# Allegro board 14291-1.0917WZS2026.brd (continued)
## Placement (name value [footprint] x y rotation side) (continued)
PR8221  0R2J-2-GP  [R402H16]  201.47 95.13 90 bottom
PR8222  20KR2F-L-GP  [R402H16]  211.14 94.18 180 bottom
PR8223  2D2R3J-2-GP  [R603H22]  207.77 102.9 180 bottom
PR8224  5K76R2F-2-GP  [R402H16]  210.31 102.65 0 bottom
PR8256  1KR2J-1-GP  [R402H16]  214.14 96.68 90 bottom
PR8257  0R2J-2-GP  [R402H16]  215.76 95.66 90 bottom
PR8258  10KR2J-3-GP  [R402H16]  214.5 95.41 0 bottom
PR8259  10KR2J-3-GP  [R402H16]  212.72 95.41 180 bottom
PR8260  13KR2F-GP  [R402H16]  214.14 97.49 90 bottom
PR8301  2D2R2F-GP  [R402H16]  141.98 154.59 270 bottom
PR8302  10KR2F-2-GP  [R402H16]  144.52 150.51 180 bottom
PR8303  7K5R2F-1-GP  [R402H16]  143.66 150.51 0 bottom
PR8304  100KR2F-L1-GP  [R402H16]  149.03 151 0 bottom
PR8305  0R2J-2-GP  [R402H16]  145.86 151.52 270 bottom
PR8306  100R2J-2-GP  [R402H14]  181.53 146.16 0 top
PR8307  100KR2J-1-GP  [R402H16]  182.31 143.76 270 top
PR8308  1KR2J-1-GP  [R402H16]  146.3 150.24 0 bottom
PR8309  100R2J-2-GP  [R402H14]  217.16 99.98 90 bottom
PR8310  100KR2J-1-GP  [R402H16]  152.09 37 270 top
PR8311  100KR2J-1-GP  [R402H16]  157.58 40.56 0 top
PR8312  330KR2J-L1-GP  [R402H16]  152.09 36.11 270 top
PR8313  100R2J-2-GP  [R402H14]  159.03 34.88 180 top
PR8314  100KR2J-1-GP  [R402H16]  156.69 40.56 0 top
PR8315  100KR2J-1-GP  [R402H16]  217.45 95.92 90 bottom
PR8316  100R2J-2-GP  [R402H14]  166.51 143.33 270 bottom
PR8317  100KR2J-1-GP  [R402H16]  172.5 142.28 270 bottom
PR8318  100R2J-2-GP  [R402H14]  166.51 140.29 270 bottom
PR8319  100KR2J-1-GP  [R402H16]  172.15 140.05 270 bottom
PR8320  0R2J-2-GP  [R402H16]  149.91 151 180 bottom
PT4501  SE220U6D3VM-38-GP  [SE361414H178]  43.68 31.77 270 bottom
PT4502  SE220U6D3VM-38-GP  [SE361414H178]  28.98 31.92 90 bottom
PT4701  SE330U2VDM-L-GP  [CT7343H83]  126.61 114.33 270 bottom
PT4702  SE33U25VM-10-GP  [SE361413H182]  146.04 145.52 270 bottom
PT4703  SE33U25VM-10-GP  [SE361413H182]  128.95 137.88 270 bottom
PT4801  SE330U2VDM-L-GP  [CT7343H83]  101.39 113.31 90 bottom
PT8206  SE330U2VDM-L-GP  [CT7343H83]  216.02 130.84 270 bottom
PT8207  SE330U2VDM-L-GP  [CT7343H83]  202.69 123.6 90 bottom
PT8208  SE330U2D5VM-14-GP  [SE361414H178]  215.89 124.49 270 bottom
PU4301  SI7121DN-T1-GE3-GP  [PPAK-8P-2H45]  98.61 156.31 270 top
PU4401  BQ24780SRUYR-GP  [QFN28-G2D7H32]  106.57 160.23 0 bottom
PU4402  SI7121DN-T1-GE3-GP  [PPAK-8P-2H45]  98.96 151.84 90 top
PU4403  SI7121DN-T1-GE3-GP  [PPAK-8P-2H45]  137.28 158.53 180 bottom
PU4404  SIS412DN-T1-GE3-GP  [PPAK-8P-2H45]  121.91 157.38 270 bottom
PU4405  SIS412DN-T1-GE3-GP  [PPAK-8P-2H45]  123.39 162.03 90 bottom
PU4501  SIS412DN-T1-GE3-GP  [PPAK-8P-2H45]  47.52 44.98 0 top
PU4502  SIS780DN-T1-GE3-GP  [PPAK-8P-2H45]  42.95 43.46 180 top
PU4503  RT6576DGQW-GP  [QFN20-G1D75H32]  39.14 55.14 0 top
PU4504  SIS412DN-T1-GE3-GP  [PPAK-8P-2H45]  30.12 44.98 0 top
PU4505  SIS412DN-T1-GE3-GP  [PPAK-8P-2H45]  34.69 43.46 180 top
PU4601  NCP81208MNTXG-2-GP  [LFQFN48J6-G4D6H40]  113.91 143.79 90 top
PU4701  NCP81382MNTXG-1-GP  [QFN36J4060-G2554H40]  124.2 129.06 90 bottom
PU4801  NCP81382MNTXG-1-GP  [QFN36J4060-G2554H40]  110.87 128.55 90 bottom
PU5001  NCP81253MNTBG-1-GP  [LFDFN8G2-G1309H40]  134.86 137.82 0 top
PU5002  SIS412DN-T1-GE3-GP  [PPAK-8P-2H45]  137.15 129.95 180 bottom
PU5003  SIS412DN-T1-GE3-GP  [PPAK-8P-2H45]  132.58 128.43 0 bottom
PU5101  TPS51716RUKR-GP  [QFN20-G1D75H32]  47.87 22.25 90 top
PU5102  SIS412DN-T1-GE3-GP  [PPAK-8P-2H45]  58.92 24.79 90 top
PU5103  SIS780DN-T1-GE3-GP  [PPAK-8P-2H45]  60.45 20.22 270 top
PU5203  TPS22961DNYT-GP  [DFN8F3-G2517H32]  150.07 121.86 270 bottom
PU5301  SY8208DQNC-GP-U  [QFN10M3-G4P-UH34]  146.71 135.56 0 bottom
PU5401  APL5930KAI-TRG-GP  [SOIC8-G3530H63]  172.21 107.47 180 bottom
PU5402  S-1339D15-M5001-GP  [SOT-23-5H52]  39.22 17.65 90 top
PU8201  RT8812AGQW-GP  [QFN20-G1D75H32]  209.04 98.33 90 bottom
PU8202  FDMS3600-02-RJK0215-COLAY-GP  [PPAK-8P-G5324H44-COLAY]  215.66 108.42 90 top
PU8204  FDMS3600-02-RJK0215-COLAY-GP  [PPAK-8P-G5324H44-COLAY]  215.66 108.43 270 bottom
PU8206  FDMS3600-02-RJK0215-COLAY-GP  [PPAK-8P-G5324H44-COLAY]  202.94 108.74 270 top
PU8208  FDMS3600-02-RJK0215-COLAY-GP  [PPAK-8P-G5324H44-COLAY]  202.94 108.74 90 bottom
PU8301  RT8068AZQWID-GP-U  [DFN10G3-G265175H32]  146.04 154.21 90 bottom
PWR1  ACES-CON4-39-GP  [50503-0040N-W01]  216.7 165.67 0 top
PWSW2  SW-TACT-130-GP-U  [TJE-533-S-V-T-R-744]  216.6 174.07 0 top
Q1701  2N7002KDW-GP  [SOT-363H44]  153.86 72.29 90 bottom
Q1702  2N7002KDW-GP  [SOT-363H44]  161.13 68.57 270 bottom
Q1801  2N7002KDW-GP  [SOT-363H44]  148.47 100.93 270 top
Q1901  2N7002K-2-GP  [SOT23DGS2D4H44]  140.8 61.26 0 top
Q2408  2N7002K-2-GP  [SOT23DGS2D4H44]  163.02 76.24 180 top
Q2412  2N7002K-2-GP  [SOT23DGS2D4H44]  193.65 65.68 270 top
Q2413  2N7002K-2-GP  [SOT23DGS2D4H44]  161.79 70.11 0 top
Q2414  2N7002K-2-GP  [SOT23DGS2D4H44]  165.35 69.91 0 top
Q2416  2N7002K-2-GP  [SOT23DGS2D4H44]  182.73 56.08 90 top
Q2505  2N7002K-2-GP  [SOT23DGS2D4H44]  69.49 5.01 270 bottom
Q2601  2N7002KDW-GP  [SOT-363H44]  159.05 76.49 90 top
Q2602  2N7002K-2-GP  [SOT23DGS2D4H44]  162.18 96.23 90 bottom
Q2603  LMBT3904LT1G-GP  [SOT23CBE2D4H44]  53.97 61.24 270 bottom
Q2604  2N7002KDW-GP  [SOT-363H44]  162 75.96 180 bottom
Q3101  2N7002K-2-GP  [SOT23DGS2D4H44]  59.35 169.83 0 top
Q3102  LMBT3904LT1G-GP  [SOT23CBE2D4H44]  47.14 163.88 270 top
Q3103  LMBT3904LT1G-GP  [SOT23CBE2D4H44]  55.32 165.43 90 top
Q3104  DMP2130L-7-GP  [SOT23DGS2D4H48]  55.65 172.01 90 top
Q4001  2N7002KDW-GP  [SOT-363H44]  52.19 31.4 90 bottom
Q4002  MMBT2222A-3-GP  [SOT23CBE2D4H44]  29.82 54.01 90 top
Q4003  DMP2130L-7-GP  [SOT23DGS2D4H48]  166.75 100 0 bottom
Q4004  2N7002K-2-GP  [SOT23DGS2D4H44]  170.52 118.91 0 bottom
Q4008  DMP2130L-7-GP  [SOT23DGS2D4H48]  44.09 9.02 270 bottom
Q4009  2N7002K-2-GP  [SOT23DGS2D4H44]  49.8 13.07 270 bottom
Q5401  LMBT3904LT1G-GP  [SOT23CBE2D4H44]  20.57 75.98 0 bottom
Q5402  2N7002KDW-GP  [SOT-363H44]  16.38 69.5 270 top
Q5403  2N7002K-2-GP  [SOT23DGS2D4H44]  22.45 69.63 180 top
Q6001  2N7002KDW-GP  [SOT-363H44]  173.38 29.33 90 top
Q6101  2N7002KDW-GP  [SOT-363H44]  155.6 52.96 90 top
Q6401  DDTA143ECA-7-F-GP  [SOT23CBE2D4H44]  180.98 121.08 90 bottom
Q6402  2N7002K-2-GP  [SOT23DGS2D4H44]  178.08 117.47 90 bottom
Q6403  DDTA143ECA-7-F-GP  [SOT23CBE2D4H44]  181.86 110.14 90 bottom
Q6404  DDTA143ECA-7-F-GP  [SOT23CBE2D4H44]  181.86 106.58 90 bottom
Q6405  DDTA143ECA-7-F-GP  [SOT23CBE2D4H44]  181.89 116.8 90 bottom
Q6406  2N7002KDW-GP  [SOT-363H44]  181.48 102.99 0 bottom
Q6407  2N7002K-2-GP  [SOT23DGS2D4H44]  177.16 121.08 90 bottom
Q6408  2N7002KDW-GP  [SOT-363H44]  181 113.46 90 bottom
Q6501  DMN3404L-7-GP  [SOT23DGS2D4H48]  196.88 115.02 180 top
Q6502  DDTA143ECA-7-F-GP  [SOT23CBE2D4H44]  195.34 118.98 270 bottom
Q6503  2N7002KDW-GP  [SOT-363H44]  53.72 73.44 90 top
Q6504  DMP2130L-7-GP  [SOT23DGS2D4H48]  46.73 77.37 270 top
Q6505  2N7002K-2-GP  [SOT23DGS2D4H44]  42.03 75.85 180 top
Q6701  2N7002KDW-GP  [SOT-363H44]  175.67 90.62 270 bottom
Q7301  2N7002K-2-GP  [SOT23DGS2D4H44]  177.31 129.16 270 bottom
Q7601  2N7002KDW-GP  [SOT-363H44]  217.63 148.99 180 bottom
Q7602  2N7002KDW-GP  [SOT-363H44]  192.34 126.87 270 bottom
Q7606  2N7002K-2-GP  [SOT23DGS2D4H44]  209.7 134.21 270 top
Q9101  DMP2130L-7-GP  [SOT23DGS2D4H48]  157.05 26.48 90 bottom
Q9102  2N7002K-2-GP  [SOT23DGS2D4H44]  156.9 30.09 90 bottom
R307  0R0402-PAD-2-GP  [0R0402-PAD-1]  15.11 12.98 90 top
R401  1KR2J-1-GP  [R402H16]  91.45 98.9 90 bottom
R402  51R2J-2-GP  [R402H16]  103.42 98.63 0 bottom
R403  499R2F-2-GP  [R402H16]  90.29 97.99 270 bottom
R404  0R0402-PAD-1-GP  [0R0402-PAD]  91.33 100.28 180 bottom
R405  10KR2J-3-GP  [R402H16]  91.21 95.53 90 bottom
R406  51R2J-2-GP  [R402H16]  100.91 103.31 0 bottom
R407  51R2J-2-GP  [R402H16]  107.11 102.4 0 bottom
R408  51R2J-2-GP  [R402H16]  105.82 101.88 0 bottom
R409  51R2J-2-GP  [R402H16]  107.12 104.69 0 bottom
R412  49D9R2F-GP  [R402H16]  125.79 64.33 0 top
R413  49D9R2F-GP  [R402H16]  126.98 64.34 0 top
R416  51R2J-2-GP  [R402H16]  105.41 103.14 270 bottom
R417  1KR2J-1-GP  [R402H16]  105.4 103.96 270 bottom
R419  1KR2J-1-GP  [R402H16]  99.77 103.11 0 bottom
R420  0R2J-2-GP  [R402H16]  98.18 106.32 90 bottom
R421  51R2J-2-GP  [R402H16]  102.79 103.56 0 bottom
R422  51R2J-2-GP  [R402H16]  103.67 104.09 0 bottom
R423  51R2J-2-GP  [R402H16]  101.98 103.56 0 bottom
R501  121R2F-GP  [R402H16]  123.4 73.15 0 top
R502  80D6R2F-L-GP  [R402H16]  124.29 73.15 0 top
R503  100R2F-L1-GP-U  [R402H14]  125.18 73.15 0 top
R504  0R0402-PAD-1-GP  [0R0402-PAD]  150.03 66.95 0 top
R505  470R2F-GP  [R402H16]  149.12 66.95 180 top
R601  49D9R2F-GP  [R402H16]  87.11 90.52 90 bottom
R602  0R0402-PAD-1-GP  [0R0402-PAD]  87.86 66.89 180 bottom
R603  100KR2J-1-GP  [R402H16]  97.38 99.47 0 bottom
R604  1KR2J-1-GP  [R402H16]  87.24 96.04 90 bottom
R605  1KR2J-1-GP  [R402H16]  90.24 93.55 90 bottom
R705  0R0603-PAD-1-GP-U  [0R0603-PAD-U]  130.04 62.13 90 top
R709  0R0402-PAD-2-GP  [0R0402-PAD-1]  98.39 100.59 0 bottom
R719  100R2F-L1-GP-U  [R402H14]  117.32 93.86 0 top
R720  100R2F-L1-GP-U  [R402H14]  116.5 93.86 180 top
R721  100R2F-L1-GP-U  [R402H14]  87.77 87.52 180 bottom
R722  100R2F-L1-GP-U  [R402H14]  87.77 85.84 180 bottom
R723  54D9R2F-L1-GP  [R402H16]  98.67 102.72 0 bottom
R726  100R2F-L1-GP-U  [R402H14]  98.39 98.86 180 bottom
R727  56R2J-4-GP  [R402H16]  99.63 100.34 180 bottom
R728  220R2J-L2-GP  [R402H16]  99.63 98.61 180 bottom
R730  100R2F-L1-GP-U  [R402H14]  120.95 81.56 180 top
R732  0R0402-PAD-2-GP  [0R0402-PAD-1]  100.48 100.33 0 bottom
R733  100R2F-L1-GP-U  [R402H14]  119.81 79.09 90 top
R734  100R2F-L1-GP-U  [R402H14]  120.12 98.63 0 bottom
R735  100R2F-L1-GP-U  [R402H14]  122.87 98.25 90 bottom
R801  24D9R2F-L-GP  [R402H16]  108.77 90.81 270 top
R802  10KR2J-3-GP  [R402H16]  141.92 93.16 180 top
R803  2K2R2J-2-GP  [R402H16]  142.82 91.22 0 top
R804  2K2R2J-2-GP  [R402H16]  142.9 93.48 0 top
R805  0R0402-PAD-2-GP  [0R0402-PAD-1]  153.91 93.94 90 top
R806  100KR2J-1-GP  [R402H16]  153.73 91.56 270 bottom
R807  0R2J-2-GP  [R402H16]  153.91 93.13 90 top
R1101  0R3J-0-U-GP  [R603H22]  147.16 103.48 90 bottom
R1102  0R3J-0-U-GP  [R603H22]  147.37 98.53 90 bottom
R1103  0R0805-PAD-1-GP-U  [0R0805-PAD-U]  152.61 117.69 270 bottom
R1104  0R3J-0-U-GP  [R603H22]  139.29 111.14 90 top
R1105  0R5J-5-GP  [R805H24]  152.61 115.86 270 bottom
R1106  0R0805-PAD-1-GP-U  [0R0805-PAD-U]  166.23 88.19 180 bottom
R1107  0R5J-5-GP  [R805H24]  155.09 120.13 0 bottom
R1108  0R0603-PAD-1-GP-U  [0R0603-PAD-U]  160.44 88.65 0 bottom
R1109  0R0603-PAD-1-GP-U  [0R0603-PAD-U]  165.22 81.48 270 bottom
R1110  0R0603-PAD-1-GP-U  [0R0603-PAD-U]  160.97 78.89 270 bottom
R1111  0R3J-0-U-GP  [R603H22]  167.11 81.9 180 bottom
R1112  0R0603-PAD-1-GP-U  [0R0603-PAD-U]  161.57 91.98 180 bottom
R1113  0R0603-PAD-1-GP-U  [0R0603-PAD-U]  159.13 88.66 180 bottom
R1114  0R0603-PAD-1-GP-U  [0R0603-PAD-U]  143.94 105.34 180 bottom
R1115  0R0603-PAD-1-GP-U  [0R0603-PAD-U]  162.72 84.22 270 bottom
R1116  0R0603-PAD-1-GP-U  [0R0603-PAD-U]  165.27 79.51 180 bottom
R1117  0R0603-PAD-1-GP-U  [0R0603-PAD-U]  148.51 115.4 270 bottom
R1118  0R3J-0-U-GP  [R603H22]  156.65 87.06 270 bottom
R1119  0R3J-0-U-GP  [R603H22]  142.67 98.73 90 bottom
R1120  0R3J-0-U-GP  [R603H22]  160.32 93.81 90 bottom
R1121  0R0603-PAD-1-GP-U  [0R0603-PAD-U]  147.01 104.84 270 bottom
R1122  0R0603-PAD-1-GP-U  [0R0603-PAD-U]  135.04 104.33 270 top
R1123  0R0603-PAD-1-GP-U  [0R0603-PAD-U]  159.79 85.52 90 bottom
R1124  0R0603-PAD-1-GP-U  [0R0603-PAD-U]  162.8 89.57 270 bottom
R1125  0R0603-PAD-1-GP-U  [0R0603-PAD-U]  140.21 104.29 270 bottom
R1126  0R0603-PAD-1-GP-U  [0R0603-PAD-U]  163.49 79.26 180 bottom
R1127  0R0603-PAD-1-GP-U  [0R0603-PAD-U]  162.8 88.15 270 bottom
R1128  0R0603-PAD-1-GP-U  [0R0603-PAD-U]  159.8 84.23 90 bottom
R1129  0R3J-0-U-GP  [R603H22]  156.65 88.34 270 bottom
R1130  0R0603-PAD-1-GP-U  [0R0603-PAD-U]  164.66 91.43 90 bottom
R1131  0R0603-PAD-1-GP-U  [0R0603-PAD-U]  134.96 104.39 90 bottom
R1132  0R0603-PAD-1-GP-U  [0R0603-PAD-U]  138.27 104.78 180 bottom
R1133  0R0603-PAD-1-GP-U  [0R0603-PAD-U]  162.84 91.98 180 bottom
R1134  0R0603-PAD-1-GP-U  [0R0603-PAD-U]  163.42 93.81 270 bottom
R1135  0R0603-PAD-1-GP-U  [0R0603-PAD-U]  159.78 86.8 90 bottom
R1136  0R3J-0-U-GP  [R603H22]  156.67 85.78 270 bottom
R1138  0R0603-PAD-1-GP-U  [0R0603-PAD-U]  154.28 88.36 270 bottom
R1139  0R0603-PAD-1-GP-U  [0R0603-PAD-U]  156.64 89.64 270 bottom
R1201  0R0402-PAD-2-GP  [0R0402-PAD-1]  124.71 38.08 180 top
R1202  0R0402-PAD-2-GP  [0R0402-PAD-1]  123.83 38.08 180 top
R1301  0R0402-PAD-2-GP  [0R0402-PAD-1]  137.52 25.81 0 top
R1302  10KR2J-3-GP  [R402H16]  139.52 25.73 180 top
R1501  100R2F-L1-GP-U  [R402H14]  132.81 93.92 90 top
R1502  200R2F-L-GP  [R402H16]  139.26 76.76 270 bottom
R1503  10KR2J-3-GP  [R402H16]  137.17 101.76 0 bottom
R1603  113R2F-GP  [R402H16]  140.39 83.6 90 top
R1604  100R2F-L1-GP-U  [R402H14]  139.65 96.27 0 bottom
R1606  10KR2J-3-GP  [R402H16]  139.69 92.88 90 bottom
R1607  10KR2J-3-GP  [R402H16]  135.84 64.23 180 bottom
R1608  10KR2J-3-GP  [R402H16]  140.13 91.62 180 bottom
R1609  10KR2J-3-GP  [R402H16]  141.93 91.21 0 top
R1701  3KR2J-2-GP  [R402H16]  136.14 102.07 180 bottom
R1702  1KR2J-1-GP  [R402H16]  151.12 73.72 90 bottom
R1703  1KR2J-1-GP  [R402H16]  153.82 66.99 270 top
R1704  0R0402-PAD-2-GP  [0R0402-PAD-1]  141.02 57.34 270 top
R1705  0R0402-PAD-1-GP  [0R0402-PAD]  153.82 66.16 270 top
R1706  0R0402-PAD-1-GP  [0R0402-PAD]  139.33 57.18 270 top
R1707  10KR2J-3-GP  [R402H16]  151.72 66.96 180 top
R1708  0R0603-PAD-1-GP-U  [0R0603-PAD-U]  166.03 70.38 180 bottom
R1709  10KR2J-3-GP  [R402H16]  159.66 65.77 270 bottom
R1710  0R2J-2-GP  [R402H16]  85.92 94.2 0 bottom
R1711  0R0603-PAD-1-GP-U  [0R0603-PAD-U]  162.78 86.83 270 bottom
R1712  0R3J-0-U-GP  [R603H22]  162.74 85.5 270 bottom
R1713  0R0402-PAD-1-GP  [0R0402-PAD]  155.09 75.06 90 bottom
R1714  10KR2J-3-GP  [R402H16]  157.57 70.53 270 top
R1715  100KR2J-1-GP  [R402H16]  154.84 74.23 90 bottom
R1716  100KR2F-L1-GP  [R402H16]  94.58 100.86 270 bottom
R1717  10KR2J-3-GP  [R402H16]  140.5 96.26 180 bottom
R1718  0R2J-2-GP  [R402H16]  135.25 48.91 270 bottom
R1719  47KR2F-GP  [R402H16]  96.11 98.23 270 bottom
R1720  0R0603-PAD-1-GP-U  [0R0603-PAD-U]  164.12 68.84 90 bottom
R1721  0R2J-2-GP  [R402H16]  161 54.97 180 top
R1722  1KR2J-1-GP  [R402H16]  95.43 100.03 270 bottom
R1723  10KR2J-3-GP  [R402H16]  153.81 67.84 270 top
R1724  0R0805-PAD-1-GP-U  [0R0805-PAD-U]  157.13 109.21 180 bottom
R1725  100KR2F-L1-GP  [R402H16]  136.95 48.91 90 bottom
R1726  10KR2J-3-GP  [R402H16]  152.86 70.35 90 bottom
R1727  100KR2J-1-GP  [R402H16]  151.57 71.64 0 bottom
R1728  0R0402-PAD-2-GP  [0R0402-PAD-1]  150.74 71.63 180 bottom
R1729  0R2J-2-GP  [R402H16]  151.13 72.9 90 bottom
R1730  330KR2J-L1-GP  [R402H16]  152.55 66.94 180 top
R1731  20KR2J-L2-GP  [R402H16]  144.17 78.74 0 top
R1732  10KR2F-2-GP  [R402H16]  138.73 58.44 0 top
R1733  10KR2J-3-GP  [R402H16]  139.63 58.45 0 top
R1734  60D4R2F-GP  [R402H16]  94.4 98.23 90 bottom
R1735  0R0805-PAD-1-GP-U  [0R0805-PAD-U]  155.22 109.21 180 bottom
R1736  0R2J-2-GP  [R402H16]  150.87 66.95 180 top
R1737  100KR2J-1-GP  [R402H16]  158.89 68.61 0 bottom
R1801  0R0402-PAD-1-GP  [0R0402-PAD]  132.69 62.23 0 bottom
R1802  1MR2J-1-GP  [R402H16]  119.9 101.09 270 bottom
R1803  2K7R2F-GP  [R402H16]  122.07 88.03 0 top
R1804  22R2J-2-GP  [R402H16]  132.2 64.42 0 top
R1805  22R2J-2-GP  [R402H16]  136.37 64.34 0 top
R1806  10R2F-L-GP  [R402H14]  144.63 66.55 0 bottom
R1807  10R2F-L-GP  [R402H14]  136.5 67.08 270 bottom
R1808  10R2F-L-GP  [R402H14]  143.8 66.54 0 bottom
R1809  10R2F-L-GP  [R402H14]  139.8 66.74 0 bottom
R1810  0R0402-PAD-1-GP  [0R0402-PAD]  119.91 101.91 270 bottom
R1811  10R2F-L-GP  [R402H14]  141.63 75.09 90 bottom
R1812  0R0402-PAD-1-GP  [0R0402-PAD]  145.47 65.46 0 bottom
R1813  0R0402-PAD-1-GP  [0R0402-PAD]  128.94 64.34 0 top
R1814  10KR2J-3-GP  [R402H16]  135.03 64.24 0 bottom
R1815  10MR2J-L-GP  [R402H16]  145.71 77.18 0 bottom
R1816  0R0402-PAD-1-GP  [0R0402-PAD]  139.34 74.2 90 bottom
R1817  10KR2J-3-GP  [R402H16]  140.5 64.36 180 top
R1818  8K2R2F-1-GP  [R402H16]  133.85 64.34 0 top
R1819  0R0402-PAD-1-GP  [0R0402-PAD]  134.69 64.34 0 top
R1820  150KR2F-L-GP  [R402H16]  148.09 83.11 90 bottom
R1821  2K2R2J-2-GP  [R402H16]  148.09 81.96 270 bottom
R1822  1KR2J-1-GP  [R402H16]  146.4 84.18 180 bottom
R1823  1KR2J-1-GP  [R402H16]  140.45 84.44 90 top
R1824  1KR2J-1-GP  [R402H16]  141.34 66.54 0 bottom
R1825  1KR2J-1-GP  [R402H16]  142.15 66.54 180 bottom
R1826  1KR2J-1-GP  [R402H16]  142.98 66.55 0 bottom
R1827  1KR2J-1-GP  [R402H16]  138.98 66.74 0 bottom
R1828  0R2J-2-GP  [R402H16]  139.33 73.36 90 bottom
R1829  10KR2J-3-GP  [R402H16]  144.53 64.25 180 top
R1830  10KR2J-3-GP  [R402H16]  143.71 64.25 180 top
R1831  10KR2J-3-GP  [R402H16]  137.19 64.34 180 top
R1832  10KR2J-3-GP  [R402H16]  139.68 64.36 180 top
R1833  10KR2J-3-GP  [R402H16]  142.76 64.24 180 top
R1834  1KR2J-1-GP  [R402H16]  138.86 67.99 90 bottom
R1835  1KR2J-1-GP  [R402H16]  140.14 75.49 180 bottom
R1836  1KR2J-1-GP  [R402H16]  139.15 75.5 0 bottom
R1901  200R2F-L-GP  [R402H16]  140.45 85.41 90 top
R1902  10KR2J-3-GP  [R402H16]  137.76 60.14 0 top
R1904  100KR2J-1-GP  [R402H16]  134.63 98.7 180 bottom
R1907  33R2J-2-GP  [R402H16]  135.25 45.67 90 bottom
R1908  0R0402-PAD-1-GP  [0R0402-PAD]  135.24 46.72 90 bottom
R1909  1KR2J-1-GP  [R402H16]  135.7 44 90 bottom
R1910  0R2J-2-GP  [R402H16]  142.74 100.37 270 top
R1911  0R0402-PAD-1-GP  [0R0402-PAD]  135.24 47.55 90 bottom
R1912  33R2J-2-GP  [R402H16]  135.25 44.84 90 bottom
R1913  0R2J-2-GP  [R402H16]  142.75 101.24 270 top
R2002  10KR2J-3-GP  [R402H16]  144.4 82.6 270 bottom
R2003  0R2J-2-GP  [R402H16]  143.32 75.06 90 bottom
R2004  0R2J-2-GP  [R402H16]  146.85 65.99 270 top
R2005  10KR2J-3-GP  [R402H16]  142.71 81.81 90 bottom
R2006  1KR2J-1-GP  [R402H16]  141.9 64.24 180 top
R2007  1KR2J-1-GP  [R402H16]  149.33 72.18 270 top
R2008  10KR2J-3-GP  [R402H16]  142.7 82.64 270 bottom
R2009  10KR2J-3-GP  [R402H16]  135.36 69.28 90 bottom
R2015  10KR2J-3-GP  [R402H16]  139.3 64.26 0 bottom
R2016  10KR2J-3-GP  [R402H16]  138.45 64.26 180 bottom
R2017  10KR2J-3-GP  [R402H16]  140.26 64.28 0 bottom
R2018  10KR2J-3-GP  [R402H16]  141.09 63.5 180 bottom
R2019  1KR2J-1-GP  [R402H16]  149.34 73.04 90 top
R2021  10KR2J-3-GP  [R402H16]  134.18 64.23 0 bottom
R2023  10KR2J-3-GP  [R402H16]  148.27 74.05 270 top
R2024  10KR2J-3-GP  [R402H16]  148.27 74.89 90 top
R2025  10KR2J-3-GP  [R402H16]  142.77 63.31 0 bottom
R2026  10KR2J-3-GP  [R402H16]  141.94 63.51 180 bottom
R2032  10KR2J-3-GP  [R402H16]  136.72 64.25 0 bottom
R2033  10KR2J-3-GP  [R402H16]  146.27 64.29 180 top
R2034  10KR2J-3-GP  [R402H16]  145.42 64.29 0 top
R2039  10KR2J-3-GP  [R402H16]  149.32 71.31 270 top
R2040  10KR2J-3-GP  [R402H16]  148.37 86.79 0 bottom
R2041  10KR2J-3-GP  [R402H16]  139.3 79.98 90 bottom
R2043  10KR2J-3-GP  [R402H16]  142.76 78.13 90 bottom
R2044  10KR2J-3-GP  [R402H16]  143.15 88.6 270 top
R2045  0R0402-PAD-1-GP  [0R0402-PAD]  136.62 68.84 180 bottom
R2046  51KR2J-1-GP  [R402H16]  144.4 81.76 90 bottom
R2047  10KR2J-3-GP  [R402H16]  143.15 87.78 270 top
R2048  51KR2J-1-GP  [R402H16]  139.3 80.8 270 bottom
R2049  51KR2J-1-GP  [R402H16]  139.84 81.63 270 bottom
R2050  10KR2J-3-GP  [R402H16]  142.69 77.28 90 bottom
R2051  10KR2J-3-GP  [R402H16]  89.28 150.93 270 bottom
R2106  0R0603-PAD-1-GP-U  [0R0603-PAD-U]  130.6 64.58 270 top
R2401  0R2J-2-GP  [R402H16]  172.45 62.66 0 top
R2402  0R0402-PAD-1-GP  [0R0402-PAD]  171.8 65.77 180 top
R2409  100KR2J-1-GP  [R402H16]  177.91 84.79 90 bottom
R2410  0R0402-PAD-1-GP  [0R0402-PAD]  172.94 87.41 180 top
R2411  0R0402-PAD-2-GP  [0R0402-PAD-1]  171.31 79.73 270 top
R2412  0R0402-PAD-2-GP  [0R0402-PAD-1]  191.47 70.22 90 top
R2414  4K7R2J-2-GP  [R402H16]  159.63 18.31 180 bottom
R2415  10KR2J-3-GP  [R402H16]  174.03 69.33 180 bottom
R2416  0R0402-PAD-1-GP  [0R0402-PAD]  161.95 73.29 0 top
R2417  100KR2J-1-GP  [R402H16]  164.56 72.21 270 top
R2418  0R2J-2-GP  [R402H16]  164.44 73.49 180 top
R2419  0R0402-PAD-1-GP  [0R0402-PAD]  191.82 78.16 90 top
R2420  10KR2J-3-GP  [R402H16]  183.68 61.75 0 top
R2421  330R2J-3-GP  [R402H16]  179.28 57.08 180 top
R2422  330R2J-3-GP  [R402H16]  182.4 67.51 180 bottom
R2423  330R2J-3-GP  [R402H16]  184.13 67.07 270 bottom
R2424  20KR2F-L-GP  [R402H16]  192.72 76.81 0 top
R2427  0R2J-2-GP  [R402H16]  191.57 83.71 90 top
R2428  0R2J-2-GP  [R402H16]  179.4 61.1 0 top
R2429  10KR2J-3-GP  [R402H16]  186.64 84.74 90 top
R2430  10KR2J-3-GP  [R402H16]  186.63 83.88 90 top
R2431  0R0402-PAD-1-GP  [0R0402-PAD]  188.6 84.33 0 top
R2432  1KR2J-1-GP  [R402H16]  190.17 63.95 90 top
R2433  100KR2J-1-GP  [R402H16]  185.16 84.55 180 top
R2434  100KR2J-1-GP  [R402H16]  191.47 71.06 270 top
R2435  0R0402-PAD-1-GP  [0R0402-PAD]  171.77 70.41 0 top
R2436  100KR2J-1-GP  [R402H16]  170.94 70.41 180 top
R2437  43R2J-GP  [R402H16]  170.62 68.83 270 top
R2438  10KR2J-3-GP  [R402H16]  191.13 67.44 0 top
R2440  0R2J-2-GP  [R402H16]  170.12 65.77 180 top
R2441  100KR2F-L1-GP  [R402H16]  184.57 53.76 90 top
R2442  64K9R2F-1-GP  [R402H16]  182.82 53.73 90 top
R2443  10KR2F-2-GP  [R402H16]  172.33 56.29 90 top
R2444  100KR2F-L1-GP  [R402H16]  173.6 54.89 0 top
R2445  0R0402-PAD-1-GP  [0R0402-PAD]  182.09 59.12 270 top
R2446  0R0603-PAD-1-GP-U  [0R0603-PAD-U]  182.63 61.93 0 top
R2448  10KR2F-2-GP  [R402H16]  191.05 76.89 0 top
R2449  100KR2J-1-GP  [R402H16]  171.3 78.91 90 top
R2450  100KR2J-1-GP  [R402H16]  171.31 78.09 270 top
R2451  100KR2J-1-GP  [R402H16]  188.91 64.35 0 top
R2452  100KR2J-1-GP  [R402H16]  188.45 59.77 90 top
R2454  100KR2J-1-GP  [R402H16]  186.35 66.67 0 bottom
R2457  0R2J-2-GP  [R402H16]  191.96 68.96 0 top
R2458  0R0402-PAD-1-GP  [0R0402-PAD]  178.57 62.13 0 top
R2462  0R0402-PAD-1-GP  [0R0402-PAD]  179.04 87.98 90 top
R2463  0R2J-2-GP  [R402H16]  155.79 18.3 0 bottom
R2464  0R2J-2-GP  [R402H16]  156.82 18.3 0 bottom
R2465  0R2J-2-GP  [R402H16]  158.74 18.31 0 bottom
R2466  0R2J-2-GP  [R402H16]  157.71 18.3 0 bottom
R2467  1KR2J-1-GP  [R402H16]  185.52 66.69 0 bottom
R2469  0R0402-PAD-1-GP  [0R0402-PAD]  190.57 62.47 180 top
R2470  0R0402-PAD-1-GP  [0R0402-PAD]  192.57 75.49 270 top
R2472  0R2J-2-GP  [R402H16]  181.47 52.92 180 top
R2473  0R0402-PAD-1-GP  [0R0402-PAD]  180.53 52.9 180 top
R2476  0R2J-2-GP  [R402H16]  154.53 17.87 90 bottom
R2478  100KR2J-1-GP  [R402H16]  171.6 76.02 270 top
R2479  0R0402-PAD-2-GP  [0R0402-PAD-1]  191.48 71.91 270 top
R2481  0R0402-PAD-1-GP  [0R0402-PAD]  182.33 88.09 0 top
R2482  0R0603-PAD-1-GP-U  [0R0603-PAD-U]  164.16 76.58 180 bottom
R2483  0R0603-PAD-1-GP-U  [0R0603-PAD-U]  159.82 76.66 0 bottom
R2484  100KR2J-1-GP  [R402H16]  191.14 65.76 180 top
R2485  10R2F-L-GP  [R402H14]  191.62 81.62 270 top
R2486  10R2F-L-GP  [R402H14]  191.62 79.91 270 top
R2487  10R2F-L-GP  [R402H14]  191.62 80.74 270 top
R2488  100KR2J-1-GP  [R402H16]  161.82 67.8 270 top
R2489  100KR2J-1-GP  [R402H16]  165.99 67.61 270 top
R2490  0R0402-PAD-1-GP  [0R0402-PAD]  191.62 79.06 270 top
R2491  0R0402-PAD-1-GP  [0R0402-PAD]  178.86 78.52 0 bottom
R2492  0R2J-2-GP  [R402H16]  170.96 65.77 180 top
R2493  0R2J-2-GP  [R402H16]  177.67 56.29 270 top
R2494  0R2J-2-GP  [R402H16]  175.89 56.29 90 top
R2495  0R2J-2-GP  [R402H16]  174.11 56.29 270 top
R2496  100KR2J-1-GP  [R402H16]  168.03 79.7 270 top
R2497  0R0402-PAD-2-GP  [0R0402-PAD-1]  177.16 52.23 270 top
R2498  100KR2J-1-GP  [R402H16]  184.36 58.62 90 top
R2499  0R0402-PAD-2-GP  [0R0402-PAD-1]  173.41 62.66 0 top
R2501  4K7R2J-2-GP  [R402H16]  147.49 56.01 270 bottom
R2502  1KR2J-1-GP  [R402H16]  69.3 7.64 0 bottom
R2503  10R2F-L-GP  [R402H14]  146.31 55.35 90 top
R2504  10MR2J-L-GP  [R402H16]  53.38 8.76 0 bottom
R2505  10R2F-L-GP  [R402H14]  140.28 54.91 0 top
R2506  10R2F-L-GP  [R402H14]  141.37 53.14 90 top
R2507  10R2F-L-GP  [R402H14]  147.49 55.17 90 bottom
R2508  10R2F-L-GP  [R402H14]  147.99 53.49 90 bottom
R2509  10R2F-L-GP  [R402H14]  152.07 52.1 0 bottom
R2510  10KR2F-2-GP  [R402H16]  175.21 84.89 180 top
R2511  10R2F-L-GP  [R402H14]  145.36 44.76 90 bottom
R2512  10R2F-L-GP  [R402H14]  145.36 43.03 90 bottom
R2513  10R2F-L-GP  [R402H14]  155.63 54.2 180 bottom
R2514  10R2F-L-GP  [R402H14]  151.39 54.6 270 bottom
R2515  4K7R2J-2-GP  [R402H16]  155.62 51.88 90 bottom
R2601  0R2J-2-GP  [R402H16]  159.35 94.87 270 bottom
R2602  0R0402-PAD-2-GP  [0R0402-PAD-1]  161.09 99.58 270 bottom
R2603  18K7R2F-GP  [R402H16]  149.27 95.43 270 bottom
R2604  2KR2F-3-GP  [R402H16]  159.53 97.59 180 bottom
R2605  0R2J-2-GP  [R402H16]  91.51 141.56 270 bottom
R2606  0R0402-PAD-2-GP  [0R0402-PAD-1]  98.36 145.54 90 top
R2607  10KR2J-3-GP  [R402H16]  161.09 100.39 270 bottom
R2608  25K5R2F-GP  [R402H16]  155.19 98.96 90 bottom
R2609  24K9R2F-L-GP  [R402H16]  155.19 99.85 90 bottom
R2610  NTC-100K-8-GP  [NTC-603H38]  153.66 99.85 0 bottom
R2611  0R0402-PAD-2-GP  [0R0402-PAD-1]  193.92 69.82 0 top
R2612  0R2J-2-GP  [R402H16]  162.38 99.95 0 bottom
R2702  0R0805-PAD-1-GP-U  [0R0805-PAD-U]  35.35 10.11 270 top
R2703  0R0603-PAD-1-GP-U  [0R0603-PAD-U]  20.93 25.66 180 top
R2704  0R0805-PAD-1-GP-U  [0R0805-PAD-U]  35.35 8.31 270 top
R2705  0R2J-2-GP  [R402H16]  25.15 8.1 180 top
R2706  0R0603-PAD-1-GP-U  [0R0603-PAD-U]  27.43 26.03 180 top
R2707  20KR2F-L-GP  [R402H16]  28.39 23.07 180 top
R2708  0R0402-PAD-2-GP  [0R0402-PAD-1]  32.23 9.75 270 top
R2709  200KR2F-L-GP  [R402H16]  29.26 22.17 180 top
R2710  0R2J-2-GP  [R402H16]  24.34 8.1 180 top
R2711  100KR2J-1-GP  [R402H16]  20.72 19.71 90 top
R2712  0R0402-PAD-2-GP  [0R0402-PAD-1]  22.06 25.5 180 top
R2713  0R0402-PAD-2-GP  [0R0402-PAD-1]  23.87 8.52 270 bottom
R2714  22R2J-2-GP  [R402H16]  33.07 13.42 270 top
R2715  0R2J-2-GP  [R402H16]  31.31 21.31 180 top
R2716  22R2J-2-GP  [R402H16]  33.87 14.69 270 top
R2717  1KR2J-1-GP  [R402H16]  32.56 23.8 0 top
R2718  22R2J-2-GP  [R402H16]  33.95 18.49 270 top
R2719  0R0402-PAD-2-GP  [0R0402-PAD-1]  35.61 19.77 0 top
R2720  22R2J-2-GP  [R402H16]  33.6 16.35 270 top
R2721  0R2J-2-GP  [R402H16]  32.47 22.07 0 top
R2722  100KR2J-1-GP  [R402H16]  29.86 24.01 270 top
R2723  0R0402-PAD-2-GP  [0R0402-PAD-1]  30.81 22.58 90 top
R2724  0R2J-2-GP  [R402H16]  32.66 11.31 0 top
R2725  0R2J-2-GP  [R402H16]  23.53 8.1 180 top
R2726  0R0402-PAD-2-GP  [0R0402-PAD-1]  22.71 8.1 180 top
R2727  0R0603-PAD-1-GP-U  [0R0603-PAD-U]  13.65 15.36 0 bottom
R2728  0R0402-PAD-2-GP  [0R0402-PAD-1]  52.1 13.83 180 bottom
R2729  0R2J-2-GP  [R402H16]  52.1 12.13 0 bottom
R2730  0R0603-PAD-1-GP-U  [0R0603-PAD-U]  29.28 25.33 90 top
R2731  0R0805-PAD-1-GP-U  [0R0805-PAD-U]  32.86 26.73 270 top
R2732  0R2J-2-GP  [R402H16]  34.21 15.52 90 top
R2906  0R0603-PAD-1-GP-U  [0R0603-PAD-U]  19.69 11.22 90 top
R2907  0R0603-PAD-1-GP-U  [0R0603-PAD-U]  13.89 11.33 270 top
R2908  10R2F-L-GP  [R402H14]  20.93 15.19 270 top
R2909  0R0603-PAD-1-GP-U  [0R0603-PAD-U]  12.11 14.98 180 top
R2910  10R2F-L-GP  [R402H14]  17.93 17.94 270 top
R2911  0R0603-PAD-1-GP-U  [0R0603-PAD-U]  16.97 9.13 180 top
R2912  4K7R2J-2-GP  [R402H16]  20.93 16 270 top
R2913  4K7R2J-2-GP  [R402H16]  17.93 18.78 270 top
R2919  10KR2J-3-GP  [R402H16]  18.99 16.01 270 top
R2920  10KR2J-3-GP  [R402H16]  18.08 23.36 180 top
R2921  1KR2J-1-GP  [R402H16]  18.94 23.37 0 top
R2922  1KR2J-1-GP  [R402H16]  18.21 21.97 270 top
R2923  0R0603-PAD-1-GP-U  [0R0603-PAD-U]  18.44 12.77 90 top
R3101  0R0603-PAD-1-GP-U  [0R0603-PAD-U]  50.23 172.55 180 top
R3102  10KR2J-3-GP  [R402H16]  43.83 163.01 0 top
R3103  10KR2J-3-GP  [R402H16]  50.82 163.06 0 top
R3104  0R0402-PAD-2-GP  [0R0402-PAD-1]  49.97 163.06 0 top
R3105  0R0603-PAD-1-GP-U  [0R0603-PAD-U]  53.07 171.33 0 top
R3106  1KR2J-1-GP  [R402H16]  51.84 167.98 270 top
R3107  15KR2J-1-GP  [R402H16]  51.86 167.06 90 top
R3108  0R0402-PAD-2-GP  [0R0402-PAD-1]  56.02 167.85 270 top
R3109  10KR2J-3-GP  [R402H16]  60.3 173.06 90 top
R3110  20KR2J-L2-GP  [R402H16]  60.3 172.18 270 top
R3111  100KR2J-1-GP  [R402H16]  60.3 167.54 90 top
R3112  2K49R2F-GP  [R402H16]  42.51 172.91 90 top
R3113  10KR2J-3-GP  [R402H16]  51.84 168.83 90 top
R3114  0R0402-PAD-2-GP  [0R0402-PAD-1]  48.75 175.97 270 top
R3605  0R0402-PAD-2-GP  [0R0402-PAD-1]  19.91 44.71 270 bottom
R3606  0R0402-PAD-2-GP  [0R0402-PAD-1]  19.91 43.9 270 bottom
R3607  0R0402-PAD-2-GP  [0R0402-PAD-1]  19.91 42.55 270 bottom
R3608  0R0402-PAD-2-GP  [0R0402-PAD-1]  19.91 41.74 270 bottom
R3609  0R0402-PAD-2-GP  [0R0402-PAD-1]  20.11 35.03 270 bottom
R3610  0R0402-PAD-2-GP  [0R0402-PAD-1]  20.11 34.17 270 bottom
R3611  0R0402-PAD-2-GP  [0R0402-PAD-1]  20.09 32.59 270 bottom
R3612  0R0402-PAD-2-GP  [0R0402-PAD-1]  20.09 31.73 270 bottom
R4002  0R0402-PAD-2-GP  [0R0402-PAD-1]  119.88 149.38 180 top
R4003  2K2R2J-2-GP  [R402H16]  32.17 54.39 0 top
R4004  100KR2J-1-GP  [R402H16]  54.38 30.58 0 bottom
R4005  1KR2J-1-GP  [R402H16]  120.77 149.38 0 top
R4006  20KR2J-L2-GP  [R402H16]  32.46 57.79 180 top
R4007  4K7R2J-2-GP  [R402H16]  32.18 56.09 0 top
R4008  10KR2J-3-GP  [R402H16]  165.84 120.46 0 bottom
R4009  4K7R2J-2-GP  [R402H16]  33.32 57.79 180 top
R4010  0R0402-PAD-2-GP  [0R0402-PAD-1]  49.52 31.27 90 bottom
R4011  0R0402-PAD-2-GP  [0R0402-PAD-1]  126.49 151.29 270 top
R4012  0R0402-PAD-2-GP  [0R0402-PAD-1]  154.4 131.76 270 bottom
R4013  10KR2J-3-GP  [R402H16]  158.46 115.69 270 bottom
R4019  100KR2J-1-GP  [R402H16]  151.65 130.55 0 bottom
R4020  100KR2J-1-GP  [R402H16]  154.51 125.9 90 bottom
R4021  0R0402-PAD-2-GP  [0R0402-PAD-1]  152.82 125.38 270 bottom
R4022  0R0402-PAD-2-GP  [0R0402-PAD-1]  151.66 128.85 0 bottom
R4023  0R2J-2-GP  [R402H16]  156.93 125.97 90 bottom
R4024  0R0402-PAD-2-GP  [0R0402-PAD-1]  158.47 116.51 270 bottom
R4025  0R1206-PAD-1-GP  [0R1206-PAD-1]  165.57 113.3 180 bottom
R4026  10KR2J-3-GP  [R402H16]  156.66 131.36 180 bottom
R4028  0R2J-2-GP  [R402H16]  157.92 125.1 90 bottom
R4029  0R0402-PAD-2-GP  [0R0402-PAD-1]  128.65 149.64 180 top
R4030  0R0402-PAD-2-GP  [0R0402-PAD-1]  127.76 149.64 180 top
R4031  100KR2J-1-GP  [R402H16]  126.87 149.64 180 top
R4032  100KR2J-1-GP  [R402H16]  125.98 149.64 180 top
R4033  0R2J-2-GP  [R402H16]  129.53 149.64 180 top
R4036  0R0402-PAD-2-GP  [0R0402-PAD-1]  154.73 114.09 0 bottom
R4037  0R0603-PAD-1-GP-U  [0R0603-PAD-U]  167 97.06 90 bottom
R4039  10KR2J-3-GP  [R402H16]  167.53 115.66 90 bottom
R4040  20KR2J-L2-GP  [R402H16]  167.53 116.55 270 bottom
R4045  0R2J-2-GP  [R402H16]  153.92 114.08 0 bottom
R4046  10KR2J-3-GP  [R402H16]  48.31 8.5 0 bottom
R4047  4K7R2J-2-GP  [R402H16]  47.89 9.83 90 bottom
R4048  0R0603-PAD-1-GP-U  [0R0603-PAD-U]  161.61 125.04 270 bottom
R4101  0R0805-PAD-1-GP-U  [0R0805-PAD-U]  153.58 85.29 90 bottom
R4102  0R2J-2-GP  [R402H16]  159.06 82.37 0 bottom
R4201  1K8R2F-GP  [R402H16]  57.64 46 270 top
R4202  2R2F-GP  [R402H16]  56.81 46.86 270 top
R4203  1K8R2F-GP  [R402H16]  55.52 39.71 180 top
R4204  0R2J-2-GP  [R402H16]  55.51 38.02 180 top
R4205  0R0402-PAD-2-GP  [0R0402-PAD-1]  57.75 37.5 90 top
R4206  1K8R2F-GP  [R402H16]  56.35 38.01 180 top
R4207  24D9R2F-L-GP  [R402H16]  56.41 40.43 0 top
R4208  2R2F-GP  [R402H16]  57.31 38.76 180 top
R4209  1K8R2F-GP  [R402H16]  56.36 48.13 180 top
R4210  0R2J-2-GP  [R402H16]  55.91 46.01 90 top
R4211  24D9R2F-L-GP  [R402H16]  57.22 48.13 180 top
R4212  0R2J-2-GP  [R402H16]  56.4 42.66 180 top
R4213  2R2F-GP  [R402H16]  58.22 43.61 0 top
R4214  1K8R2F-GP  [R402H16]  55.52 43.6 180 top
R4215  24D9R2F-L-GP  [R402H16]  56.41 44.42 0 top
R4216  1K8R2F-GP  [R402H16]  57.34 42.66 180 top
R5401  0R0402-PAD-2-GP  [0R0402-PAD-1]  16 65.31 90 bottom
R5402  0R0402-PAD-2-GP  [0R0402-PAD-1]  16 64.42 90 bottom
R5403  0R0402-PAD-2-GP  [0R0402-PAD-1]  16 67.47 90 bottom
R5404  0R0402-PAD-2-GP  [0R0402-PAD-1]  16 66.58 90 bottom
R5405  0R0402-PAD-2-GP  [0R0402-PAD-1]  16 60.99 90 bottom
R5406  0R0402-PAD-2-GP  [0R0402-PAD-1]  16 60.1 90 bottom
R5407  0R0402-PAD-2-GP  [0R0402-PAD-1]  16 63.15 90 bottom
R5408  0R0402-PAD-2-GP  [0R0402-PAD-1]  16 62.26 90 bottom
R5409  0R0603-PAD-1-GP-U  [0R0603-PAD-U]  22.6 72.8 90 bottom
R5410  200KR2F-L-GP  [R402H16]  17.93 76.53 270 bottom
R5411  150KR2F-L-GP  [R402H16]  17.93 77.42 270 bottom
R5412  10KR2J-3-GP  [R402H16]  20.44 78.52 90 bottom
R5413  100KR2J-1-GP  [R402H16]  13.46 76.79 180 top
R5414  150R2J-L1-GP-U  [R402H16]  14.73 64.88 180 bottom
R5415  150R2J-L1-GP-U  [R402H16]  14.73 60.56 180 bottom
R5416  150R2J-L1-GP-U  [R402H16]  14.73 62.72 180 bottom
R5417  150R2J-L1-GP-U  [R402H16]  14.73 67.01 180 bottom
R5418  0R2J-2-GP  [R402H16]  20.21 69.32 0 top
R5419  0R0402-PAD-2-GP  [0R0402-PAD-1]  22.19 78.52 90 bottom
R5501  0R3J-0-U-GP  [R603H22]  98.67 148.8 90 top
R5506  100KR2J-1-GP  [R402H16]  78.85 156.42 180 bottom
R5518  100R2J-2-GP  [R402H14]  72.49 177.56 90 bottom
R5519  100R2J-2-GP  [R402H14]  72.48 176.71 90 bottom
R5520  0R3J-0-U-GP  [R603H22]  73.91 158.91 0 bottom
R5521  10KR2J-3-GP  [R402H16]  75.05 168.81 90 bottom
R5522  0R3J-0-U-GP  [R603H22]  76.7 158.91 0 bottom
R5523  0R5J-5-GP  [R805H24]  81.72 159.55 90 bottom
R5524  0R2J-2-GP  [R402H16]  74.88 165.08 90 bottom
R5525  100R2J-2-GP  [R402H14]  80.75 167.06 90 top
R5526  0R2J-2-GP  [R402H16]  80.64 167.87 270 top
R5527  0R0603-PAD-1-GP-U  [0R0603-PAD-U]  75.31 158.91 0 bottom
R5528  100KR2J-1-GP  [R402H16]  79.88 174.39 180 top
R5529  100KR2J-1-GP  [R402H16]  79.88 172.62 0 top
R5530  0R0402-PAD-2-GP  [0R0402-PAD-1]  74.9 164.23 90 bottom
R5531  0R0402-PAD-2-GP  [0R0402-PAD-1]  77.72 164.88 90 bottom
R5532  0R5J-5-GP  [R805H24]  78.27 158.99 0 bottom
R5535  0R0402-PAD-2-GP  [0R0402-PAD-1]  81.99 157.13 90 top
R5536  0R0402-PAD-2-GP  [0R0402-PAD-1]  81.99 156.19 90 top
R5537  100R2J-2-GP  [R402H14]  84.69 152.61 180 top
R5538  100R2J-2-GP  [R402H14]  80.91 152.19 270 top
R5539  0R0402-PAD-2-GP  [0R0402-PAD-1]  80.75 166.24 90 top
R5540  0R0402-PAD-2-GP  [0R0402-PAD-1]  91.1 150.93 90 bottom
R6002  330KR2J-L1-GP  [R402H16]  160.03 26.11 90 top
R6003  100KR2J-1-GP  [R402H16]  160.02 25.19 90 top
R6004  0R2J-2-GP  [R402H16]  177.18 28.63 0 top
R6005  100KR2J-1-GP  [R402H16]  175.61 28.65 0 top
R6006  0R0805-PAD-1-GP-U  [0R0805-PAD-U]  180.14 33.2 180 bottom
R6007  0R0402-PAD-2-GP  [0R0402-PAD-1]  184.3 33.77 180 bottom
R6101  100KR2J-1-GP  [R402H16]  157.81 52.53 0 top
R6102  100KR2J-1-GP  [R402H16]  153.33 53.45 0 top
R6103  330KR2J-L1-GP  [R402H16]  163.14 57.92 270 top
R6104  0R0402-PAD-2-GP  [0R0402-PAD-1]  157.81 54.23 0 top
R6105  10KR2J-3-GP  [R402H16]  159.1 54.69 270 top
R6108  0R2J-2-GP  [R402H16]  171.24 55.3 270 top
R6109  0R2J-2-GP  [R402H16]  171.25 53.51 270 top
R6110  0R0402-PAD-2-GP  [0R0402-PAD-1]  156.68 67 0 bottom
R6111  0R0402-PAD-2-GP  [0R0402-PAD-1]  157.66 66.95 0 bottom
R6112  0R0402-PAD-2-GP  [0R0402-PAD-1]  162.51 50.04 90 top
R6113  0R0402-PAD-2-GP  [0R0402-PAD-1]  163.38 55.02 0 top
R6114  0R0402-PAD-2-GP  [0R0402-PAD-1]  162.52 55 0 top
R6115  0R2J-2-GP  [R402H16]  171.25 52.65 270 top
R6116  0R0402-PAD-2-GP  [0R0402-PAD-1]  164.22 55.01 0 top
R6118  0R2J-2-GP  [R402H16]  168.75 39.25 270 top
R6119  0R2J-2-GP  [R402H16]  171.25 54.42 270 top
R6121  0R0402-PAD-2-GP  [0R0402-PAD-1]  163.54 48.7 90 top
R6401  330R2J-3-GP  [R402H16]  184.76 123.42 270 bottom
R6402  10KR2J-3-GP  [R402H16]  183.29 113.88 0 bottom
R6403  100R2J-2-GP  [R402H14]  217.34 149.89 270 top
R6404  0R0402-PAD-2-GP  [0R0402-PAD-1]  183.46 103.92 0 bottom
R6405  0R0402-PAD-2-GP  [0R0402-PAD-1]  179.32 108.59 0 bottom
R6406  330R2J-3-GP  [R402H16]  184.65 107.47 270 bottom
R6407  470R2J-2-GP  [R402H16]  184.65 111.03 270 bottom
R6408  100R2J-2-GP  [R402H14]  219.27 152.84 180 top
R6409  330R2J-3-GP  [R402H16]  184.3 121.5 0 bottom
R6503  51KR2J-1-GP  [R402H16]  196.26 109.07 0 top
R6504  0R3J-0-U-GP  [R603H22]  195.47 106.9 0 top
R6505  100KR2J-1-GP  [R402H16]  199.11 115.76 0 top
R6506  1KR2J-1-GP  [R402H16]  192.49 118.95 90 bottom
R6507  100KR2J-1-GP  [R402H16]  195.81 110.34 270 top
R6508  0R0402-PAD-2-GP  [0R0402-PAD-1]  197.66 117.93 0 bottom
R6509  100KR2J-1-GP  [R402H16]  55.37 77.63 90 top
R6511  0R2J-2-GP  [R402H16]  51.05 71.15 90 top
R6512  0R0402-PAD-2-GP  [0R0402-PAD-1]  51.05 73.56 270 top
R6513  4K7R2J-2-GP  [R402H16]  56.51 71.66 0 top
R6514  10KR2J-3-GP  [R402H16]  55.37 76.74 270 top
R6515  0R2J-2-GP  [R402H16]  51.05 70.26 90 top
R6516  1KR2J-1-GP  [R402H16]  44.32 78.13 0 top
R6517  0R3J-0-U-GP  [R603H22]  47.24 74.83 90 top
R6518  0R2J-2-GP  [R402H16]  50.92 75.74 90 top
R6519  0R2J-2-GP  [R402H16]  50.92 74.86 90 top
R6520  0R2J-2-GP  [R402H16]  44.68 74.98 90 top
R6521  0R0402-PAD-2-GP  [0R0402-PAD-1]  39.78 74.78 0 top
R6522  100R3J-4-GP  [R603H22]  47.24 73.44 270 top
R6701  0R0603-PAD-1-GP-U  [0R0603-PAD-U]  175.01 95.49 90 bottom
R6702  100KR2J-1-GP  [R402H16]  170.81 90.58 0 bottom
R6703  100KR2J-1-GP  [R402H16]  176.67 95.05 180 bottom
R6704  100KR2J-1-GP  [R402H16]  171.7 90.58 0 bottom
R6705  100KR2J-1-GP  [R402H16]  174.52 93.07 90 bottom
R6706  0R2J-2-GP  [R402H16]  173.48 90.58 0 bottom
R6707  1MR2J-1-GP  [R402H16]  172.59 90.58 180 bottom
R6801  0R2J-2-GP  [R402H16]  166.92 39.96 90 bottom
R6802  0R2J-2-GP  [R402H16]  165.14 39.53 270 bottom
R7301  2K49R2F-GP  [R402H16]  178.35 153.62 90 bottom
R7302  10KR2F-2-GP  [R402H16]  141.95 151.08 0 bottom
R7303  10KR2J-3-GP  [R402H16]  176.86 131.41 270 bottom
R7304  0R2J-2-GP  [R402H16]  180.33 124.64 180 bottom
R7305  0R2J-2-GP  [R402H16]  175 129.6 0 bottom
R7306  100KR2F-L1-GP  [R402H16]  181.19 124.64 0 bottom
R7307  200R2F-L-GP  [R402H16]  178.78 146.58 180 bottom
R7308  0R2J-2-GP  [R402H16]  186.56 127.66 90 bottom
R7312  10KR2J-3-GP  [R402H16]  187.83 128.11 180 bottom
R7313  0R2J-2-GP  [R402H16]  182.09 124.62 0 bottom
R7501  60D4R2F-GP  [R402H16]  199.1 148.55 0 top
R7503  60D4R2F-GP  [R402H16]  196.8 147.27 270 top
R7505  40D2R2F-GP  [R402H16]  202.67 150.53 90 top
R7506  51D1R2F-GP  [R402H16]  204.39 154.28 270 top
R7507  42D2R2F-GP  [R402H16]  201.75 152 90 top
R7508  10KR2F-2-GP  [R402H16]  194.84 153.67 0 top
R7509  10KR2F-2-GP  [R402H16]  179.93 176.05 0 bottom
R7510  10KR2F-2-GP  [R402H16]  198.62 151.33 270 top
R7511  10KR2F-2-GP  [R402H16]  193.42 153.65 0 top
R7512  10KR2F-2-GP  [R402H16]  202.68 154.68 90 top
R7518  10KR2J-3-GP  [R402H16]  199.03 133.71 0 top
R7519  0R2J-2-GP  [R402H16]  200.95 135.79 90 top
R7601  10KR2J-3-GP  [R402H16]  207 137.9 180 bottom
R7602  10KR2J-3-GP  [R402H16]  201.77 139.88 90 top
R7603  1MR2J-1-GP  [R402H16]  207.84 138.97 180 bottom
R7604  1K3R2J-GP  [R402H16]  207.84 137.27 0 bottom
R7605  100KR2J-1-GP  [R402H16]  205.18 135.62 270 top
R7606  10KR2F-2-GP  [R402H16]  202.68 132.22 90 top
R7607  40K2R2F-GP  [R402H16]  198.7 135.6 90 top
R7608  4K99R2F-L-GP  [R402H16]  211.32 140.26 90 bottom
R7609  10KR2J-3-GP  [R402H16]  202.72 128.26 180 bottom
R7610  100KR2J-1-GP  [R402H16]  207.8 132.95 270 bottom
R7611  4K99R2F-L-GP  [R402H16]  209.19 143.36 0 bottom
R7612  10KR2J-3-GP  [R402H16]  194.66 126.9 180 bottom
R7613  10KR2J-3-GP  [R402H16]  189.98 126.46 180 bottom
R7614  10KR2F-2-GP  [R402H16]  209.6 140.26 90 bottom
R7615  10KR2J-3-GP  [R402H16]  200.56 128.68 270 bottom
R7616  20KR2F-L-GP  [R402H16]  212.16 141.23 90 bottom
R7617  10KR2J-3-GP  [R402H16]  199.44 139.04 90 top
R7618  10KR2F-2-GP  [R402H16]  208.35 141.66 0 bottom
R7619  4K99R2F-L-GP  [R402H16]  209.19 141.66 0 bottom
R7620  10KR2F-2-GP  [R402H16]  208.35 143.36 180 bottom
R7621  10KR2J-3-GP  [R402H16]  207.42 127.96 0 bottom
R7622  10KR2J-3-GP  [R402H16]  205.2 128.26 180 bottom
R7623  0R2J-2-GP  [R402H16]  201.01 136.61 90 top
R7625  10KR2J-3-GP  [R402H16]  208.67 128.39 90 bottom
R7626  10KR2J-3-GP  [R402H16]  202.86 141.15 0 top
R7627  10KR2J-3-GP  [R402H16]  202.74 136.33 90 top
R7628  10KR2J-3-GP  [R402H16]  207.01 136.21 180 bottom
R7629  0R2J-2-GP  [R402H16]  207.28 139.43 90 top
R7630  0R2J-2-GP  [R402H16]  203.93 133.51 0 top
R7631  10KR2J-3-GP  [R402H16]  202.66 133.05 90 top
R7632  10KR2J-3-GP  [R402H16]  207.65 129.66 180 bottom
R7633  10KR2J-3-GP  [R402H16]  207.71 130.93 90 bottom
R7634  10KR2J-3-GP  [R402H16]  209.99 129.96 90 bottom
R7635  10KR2J-3-GP  [R402H16]  203.57 128.26 0 bottom
R7636  0R2J-2-GP  [R402H16]  207.7 131.8 270 bottom
R7637  10KR2J-3-GP  [R402H16]  203.05 131.37 90 top
R7638  30K1R2F-L-GP  [R402H16]  212.16 142.07 90 bottom
R7639  24K9R2F-L-GP  [R402H16]  210.87 141.66 180 bottom
R7640  4K99R2F-L-GP  [R402H16]  210.03 141.66 180 bottom
R7642  15KR2F-GP  [R402H16]  207.51 141.66 0 bottom
R7643  10KR2J-3-GP  [R402H16]  207.28 138.59 90 top
R7644  10KR2J-3-GP  [R402H16]  210.33 131.57 180 top
R7645  10KR2J-3-GP  [R402H16]  189.53 124.32 270 bottom
R7646  45K3R2F-L-GP  [R402H16]  208.67 127.56 90 bottom
R7647  4K99R2F-L-GP  [R402H16]  204.39 128.26 180 bottom
R7648  10KR2J-3-GP  [R402H16]  212.04 133.86 0 top
R7649  10KR2J-3-GP  [R402H16]  209.5 131.57 0 top
R7650  4K99R2F-L-GP  [R402H16]  201.83 128.25 180 bottom
R7653  0R2J-2-GP  [R402H16]  193.17 124.86 90 bottom
R7654  45K3R2F-L-GP  [R402H16]  206.78 129.68 180 bottom
R7655  45K3R2F-L-GP  [R402H16]  206.67 141.66 0 bottom
R7656  0R2J-2-GP  [R402H16]  191.47 124.03 270 bottom
R7657  0R2J-2-GP  [R402H16]  218.89 146.58 90 bottom
R7806  1K33R2F-GP  [R402H16]  199.05 161.12 180 bottom
R7807  1K33R2F-GP  [R402H16]  200.32 160.71 270 bottom
R7808  243R2F-2-GP  [R402H16]  202.23 161.12 180 top
R7809  243R2F-2-GP  [R402H16]  199.73 176.11 0 top
R7810  162R2F-GP  [R402H16]  201.04 175.67 90 top
R7903  1K33R2F-GP  [R402H16]  177.79 175.67 270 bottom
R7904  1K33R2F-GP  [R402H16]  179.06 176.05 0 bottom
R7912  243R2F-2-GP  [R402H16]  181.59 161.56 270 top
R7913  243R2F-2-GP  [R402H16]  181.38 176.07 0 top
R7914  162R2F-GP  [R402H16]  180.08 175.54 270 top
R8301  0R6J-3-GP  [R1206H28]  171.21 129.13 90 bottom
R8302  0R2J-2-GP  [R402H16]  170.06 145.51 180 top
R8303  0R2J-2-GP  [R402H16]  152.53 38.39 0 top
R8304  1MR2J-1-GP  [R402H16]  153.54 38.39 180 top
R8305  750KR2J-GP  [R402H16]  154.91 36.09 270 top
R8306  0R2J-2-GP  [R402H16]  170.53 137.42 90 bottom
R9101  0R0603-PAD-1-GP-U  [0R0603-PAD-U]  169.55 19.12 180 bottom
R9102  10KR2J-3-GP  [R402H16]  160.89 25.41 90 bottom
R9103  10KR2J-3-GP  [R402H16]  165.83 20.35 180 bottom
R9104  10KR2J-3-GP  [R402H16]  167.96 20.75 270 bottom
R9105  33R2J-2-GP  [R402H16]  165.29 18.19 90 bottom
R9106  33R2J-2-GP  [R402H16]  162.64 20.83 0 bottom
R9107  33R2J-2-GP  [R402H16]  166.64 20.35 0 bottom
R9108  0R3J-0-U-GP  [R603H22]  159.59 27.03 180 bottom
R9109  0R0603-PAD-1-GP-U  [0R0603-PAD-U]  160.34 31.21 90 bottom
R9110  0R3J-0-U-GP  [R603H22]  165.85 30.7 0 bottom
R9111  0R0603-PAD-1-GP-U  [0R0603-PAD-U]  172.28 21.75 180 bottom
R9112  0R0603-PAD-1-GP-U  [0R0603-PAD-U]  163.69 20.69 180 bottom
R9113  0R0603-PAD-1-GP-U  [0R0603-PAD-U]  162.93 30.57 90 bottom
R9114  0R0603-PAD-1-GP-U  [0R0603-PAD-U]  167.13 30.7 0 bottom
R9115  100R2F-L1-GP-U  [R402H14]  156.92 23.25 270 bottom
R9116  0R3J-0-U-GP  [R603H22]  170.54 26.7 0 bottom
R9117  10KR2J-3-GP  [R402H16]  159.95 29.21 0 bottom
R9118  10KR2J-3-GP  [R402H16]  164.56 30.35 180 bottom
R9119  10KR2J-3-GP  [R402H16]  160.66 26.81 180 bottom
R9120  10KR2J-3-GP  [R402H16]  158.3 24.25 270 bottom
R9201  0R2J-2-GP  [R402H16]  180.66 124.95 180 top
R9202  0R0402-PAD-2-GP  [0R0402-PAD-1]  179.76 124.92 0 top
R9203  0R0402-PAD-2-GP  [0R0402-PAD-1]  177.07 124.55 180 top
R9204  0R0402-PAD-2-GP  [0R0402-PAD-1]  177.9 124.54 180 top
R9804  4K7R2F-GP  [R402H16]  177.41 12.98 270 bottom
R9918  0R2J-2-GP  [R402H16]  127.63 28.48 270 top
R9920  0R2J-2-GP  [R402H16]  127.63 29.37 270 top
R9926  0R2J-2-GP  [R402H16]  129.56 65.19 180 bottom
R9927  0R0402-PAD-2-GP  [0R0402-PAD-1]  104.77 101.7 0 bottom
R9928  0R0402-PAD-2-GP  [0R0402-PAD-1]  104.96 105.29 90 bottom
R9930  0R0402-PAD-2-GP  [0R0402-PAD-1]  100.08 104.89 0 bottom
R9935  0R0402-PAD-2-GP  [0R0402-PAD-1]  102.42 105.65 270 bottom
RJ45  PAD-RJ45-8P-186-1-GP  [PAD-23-00980-2A03-A-1]  4 171.22 90 bottom
RN801  SRN2K2J-1-GP  [ARES2H16]  137.54 99.38 0 bottom
RN1602  SRN10KJ-6-GP  [ARES8-CN24-MUH20]  132.79 98.85 0 bottom
RN1702  SRN0J-6-GP  [SMD-ARES4H20]  168.38 69.94 270 bottom
RN1806  SRN0J-7-GP-U  [ARES8-CN24H22]  131.47 64.55 0 bottom
RN1807  SRN2K2J-4-GP  [ARES8-CN24-UH20]  144.5 85.46 270 bottom
RN1810  SRN10KJ-5-GP  [ARES2H18]  152.53 101.06 270 top
RN1811  SRN2K2J-1-GP  [ARES2H16]  148.21 98.36 90 top
RN1901  SRN20KJ-1-GP  [SMD-ARES4H20]  135.36 59.07 0 top
RN2007  SRN10KJ-5-GP  [ARES2H18]  146.97 91.56 90 bottom
RN2008  SRN2K2J-1-GP  [ARES2H16]  146.97 89.52 90 bottom
RN2009  SRN10KJ-5-GP  [ARES2H18]  152.68 90.81 90 top
RN2402  SRN4K7J-8-GP  [SMD-ARES4H18]  185.4 70.08 180 bottom
RN2403  SRN100KJ-5-GP  [ARES8-CN24H20]  195.32 114.84 270 bottom
RN2404  SRN100KJ-5-GP  [ARES8-CN24H20]  194.84 111.16 270 bottom
RN2409  SRN100KJ-5-GP  [ARES8-CN24H20]  193.97 105.96 270 bottom
RN2410  SRN100KJ-5-GP  [ARES8-CN24H20]  193.77 102.63 270 bottom
RN2411  SRN10KJ-6-GP  [ARES8-CN24-MUH20]  194.99 92.74 270 bottom
RN2412  SRN10KJ-6-GP  [ARES8-CN24-MUH20]  193.66 98.09 270 bottom
RN2501  SRN4K7J-8-GP  [SMD-ARES4H18]  150.49 69.68 90 bottom
RN2502  SRN4K7J-8-GP  [SMD-ARES4H18]  153.64 52.45 180 bottom
RN2602  SRN2K2J-1-GP  [ARES2H16]  159.45 79.63 180 top
RN2603  SRN10KJ-5-GP  [ARES2H18]  188.32 74.86 0 bottom
RN2701  SRN0J-6-GP  [SMD-ARES4H20]  38.33 21.48 0 top
RN2901  SRN2K2J-1-GP  [ARES2H16]  26.95 22.4 180 top
RN3101  SRN10KJ-5-GP  [ARES2H18]  55.66 162.59 270 top
RN3201  SRN75J-1-GP  [ARES8-CN24H22]  18.41 172.24 270 top
RN4302  SRN100J-4-GP  [ARES8-CN24H20]  157.35 172.24 0 top
RN5401  SRN2K2J-1-GP  [ARES2H16]  16.38 72.67 0 top
RN5402  SRN470J-3-GP  [ARES8-CN24H20]  18.94 61.65 90 top
RN5403  SRN470J-3-GP  [ARES8-CN24H20]  18.94 65.92 90 top
RN5502  SRN100KJ-5-GP  [ARES8-CN24H20]  69.04 167.48 90 bottom
RN5503  SRN100J-4-GP  [ARES8-CN24H20]  75.09 166.93 270 bottom
RN5504  SRN33J-5-GP-U  [SMD-ARES4H18]  81.09 163.8 180 top
RN5505  SRN33J-5-GP-U  [SMD-ARES4H18]  84.63 166 180 bottom
RN6502  SRN2K2J-1-GP  [ARES2H16]  53.59 70.77 90 top
RN6503  SRN33J-5-GP-U  [SMD-ARES4H18]  54.22 79.4 270 top
RN6504  SRN10KJ-5-GP  [ARES2H18]  50.16 79.53 270 top
RN6801  SRN0J-7-GP-U  [ARES8-CN24H22]  176.5 40.33 270 bottom
RN7401  SRN10KJ-5-GP  [ARES2H18]  188.17 128.2 0 top
RN7402  SRN10KJ-5-GP  [ARES2H18]  186.12 128.08 0 top
RN7403  SRN10KJ-5-GP  [ARES2H18]  198.62 137.33 90 top
RN7404  SRN10KJ-5-GP  [ARES2H18]  190.28 128.82 0 top
RN7601  SRN4K7J-8-GP  [SMD-ARES4H18]  217.73 151.93 90 bottom
RN7602  SRN10KJ-5-GP  [ARES2H18]  176.75 132.87 90 bottom
RN7603  SRN2K2J-1-GP  [ARES2H16]  209.9 131.93 180 bottom
RN7604  SRN2K2J-1-GP  [ARES2H16]  210.14 134.46 270 bottom
RN7605  SRN2K2J-1-GP  [ARES2H16]  207.43 137.16 90 top
RTC1  ACES-CON2-11-GP-U  [87213-0020N-W02]  63.5 8.17 90 bottom
SKT25  SKT-G6179HT0321-001-GP  [G6179HT0321-001]  140.53 54.99 90 bottom
SKT26  SKT-G6179HT0321-001-GP  [G6179HT0321-001]  152.28 45.68 90 bottom
SPI25  W25Q128FVSIG-GP  [SOIC8-1H86]  140.53 54.99 270 bottom
SPI252  W25Q64FVSSIQ-GP  [SOIC8-1H86]  152.28 45.68 270 bottom
SPK1  ACES-CON4-29-GP  [50224-0040N-001]  66.9 9.77 270 top
SPR1  SPRING-31-GP  [SPR7345H154]  82.9 59.27 270 top
SPR2  SPRING-24-GP-U  [SPR5230H134]  80.4 79.57 0 bottom
SPR3  SPRING-13-GP-U  [SPR7837H229]  151.9 35.02 90 bottom
TC1201  ST330U2VDM-4-GP-U  [CT7343H83]  66.16 41.94 270 top
TC3501  SC100U6D3V6MX-GP  [C1206H71]  24.51 43.34 90 top
TC3502  SC100U6D3V6MX-GP  [C1206H71]  17.95 35.76 180 top
THM26  NCT7718W-GP  [MSOP8-1H44]  154.8 96.34 270 bottom
TP401  TPAD14-OP-GP  [TPAD14-OP]  101.37 99.06 180 bottom
TP402  TPAD14-OP-GP  [TPAD14-OP]  92.93 98.53 180 bottom
TP403  TPAD14-OP-GP  [TPAD14-OP]  139.16 98.21 180 bottom
TP404  TPAD14-OP-GP  [TPAD14-OP]  135.63 70.57 0 top
TP501  TPAD14-OP-GP  [TPAD14-OP]  106.42 76.23 0 top
TP502  TPAD14-OP-GP  [TPAD14-OP]  110.68 78.42 0 top
TP601  TPAD14-OP-GP  [TPAD14-OP]  91.48 67.83 180 bottom
TP602  TPAD14-OP-GP  [TPAD14-OP]  91.53 66.59 180 bottom
TP603  TPAD14-OP-GP  [TPAD14-OP]  92.76 66.57 180 bottom
TP604  TPAD14-OP-GP  [TPAD14-OP]  92.7 67.8 180 bottom
TP605  TPAD14-OP-GP  [TPAD14-OP]  127.57 78.17 0 top
TP606  TPAD14-OP-GP  [TPAD14-OP]  130.05 80.29 0 top
TP607  TPAD14-OP-GP  [TPAD14-OP]  136.79 71 270 top
TP608  TPAD14-OP-GP  [TPAD14-OP]  133.19 76.18 270 top
TP609  TPAD14-OP-GP  [TPAD14-OP]  133.29 71.93 0 top
TP610  TPAD14-OP-GP  [TPAD14-OP]  135 71.65 0 top
TP611  TPAD14-OP-GP  [TPAD14-OP]  137.64 69.1 180 bottom
TP612  TPAD14-OP-GP  [TPAD14-OP]  98.46 90.69 0 top
TP613  TPAD14-OP-GP  [TPAD14-OP]  99.69 90.8 0 top
TP614  TPAD14-OP-GP  [TPAD14-OP]  94.11 74.09 0 top
TP615  TPAD14-OP-GP  [TPAD14-OP]  95.34 74.14 0 top
TP616  TPAD14-OP-GP  [TPAD14-OP]  103.33 76.91 0 top
TP617  TPAD14-OP-GP  [TPAD14-OP]  103.46 78.15 0 top
TP704  TPAD14-OP-GP  [TPAD14-OP]  100.85 89.73 0 top
TP708  TPAD14-OP-GP  [TPAD14-OP]  101.51 90.82 0 top
TP801  TPAD14-OP-GP  [TPAD14-OP]  108.34 101.06 270 bottom
TP802  TPAD14-OP-GP  [TPAD14-OP]  129.06 88.14 0 top
TP1601  TPAD14-OP-GP  [TPAD14-OP]  139.32 93.93 180 bottom
TP1602  TPAD14-OP-GP  [TPAD14-OP]  139.09 91.85 180 bottom
TP1603  TPAD14-OP-GP  [TPAD14-OP]  140.61 93.91 180 bottom
TP1703  TPAD14-OP-GP  [TPAD14-OP]  129.69 61.69 180 bottom
TP1704  TPAD14-OP-GP  [TPAD14-OP]  127.18 74.45 0 top
TP1706  TPAD14-OP-GP  [TPAD14-OP]  127.57 76.22 0 top
TP1707  TPAD14-OP-GP  [TPAD14-OP]  130.11 74.68 0 top
TP1708  TPAD14-OP-GP  [TPAD14-OP]  132.12 79.86 0 top
TP1801  TPAD14-OP-GP  [TPAD14-OP]  142.52 90.81 180 bottom
TP1804  TPAD14-OP-GP  [TPAD14-OP]  145.15 87.47 180 bottom
TP1805  TPAD14-OP-GP  [TPAD14-OP]  143.92 87.47 180 bottom
TP1806  TPAD14-OP-GP  [TPAD14-OP]  138.99 89.56 180 bottom
TP1902  TPAD14-OP-GP  [TPAD14-OP]  134.41 69.8 0 top
TP2006  TPAD14-OP-GP  [TPAD14-OP]  140.25 87.39 180 bottom
TP2009  TPAD14-OP-GP  [TPAD14-OP]  134.16 83.18 0 top
TP2012  TPAD14-OP-GP  [TPAD14-OP]  141.47 87.42 180 bottom
TP2013  TPAD14-OP-GP  [TPAD14-OP]  142.69 87.41 180 bottom
TP2014  TPAD14-OP-GP  [TPAD14-OP]  139.01 87.3 180 bottom
